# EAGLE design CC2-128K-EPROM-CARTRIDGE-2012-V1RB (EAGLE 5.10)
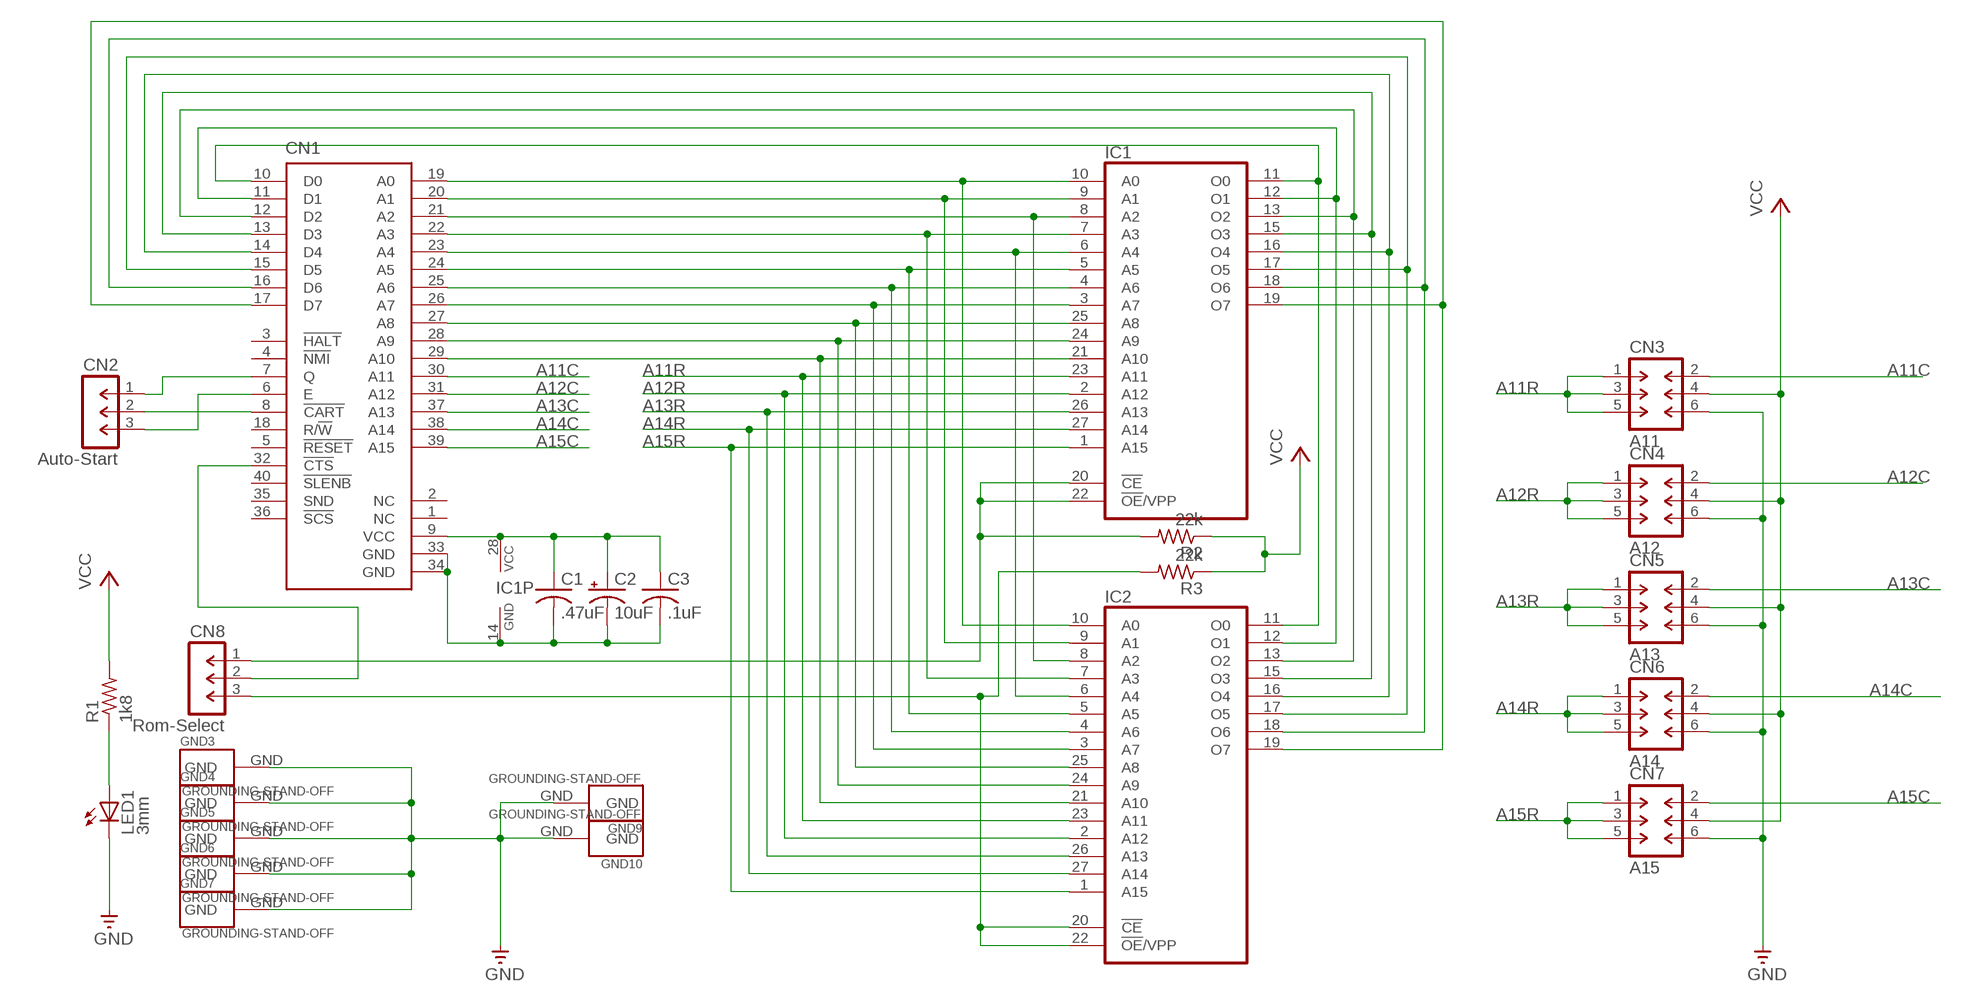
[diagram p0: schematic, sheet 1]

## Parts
C1  .47uF  NP-CAPACITOR-C050-025X075  [C050-025X075]
C2  10uF  P-CAPACITOR-CPOL-RADIAL-1  [CPOL-RADIAL-1]
C3  .1uF  NP-CAPACITOR-C050-025X075  [C050-025X075]
CN1  COCO3-CARTRIDGE-PLUG-MEDIUM  [EDGE-CARD-PLUG-40-MEDIUM]
CN2  Auto-Start  1X03-SIP-100-32  [SIL1X03-100]
CN3  A11  2X03-DIL-100-32  [DIL2X03-100]
CN4  A12  2X03-DIL-100-32  [DIL2X03-100]
CN5  A13  2X03-DIL-100-32  [DIL2X03-100]
CN6  A14  2X03-DIL-100-32  [DIL2X03-100]
CN7  A15  2X03-DIL-100-32  [DIL2X03-100]
CN8  Rom-Select  1X03-SIP-100-32  [SIL1X03-100]
GND3  GROUNDING-STAND-OFF  [STAND-OFF]
GND4  GROUNDING-STAND-OFF  [STAND-OFF]
GND5  GROUNDING-STAND-OFF  [STAND-OFF]
GND6  GROUNDING-STAND-OFF  [STAND-OFF]
GND7  GROUNDING-STAND-OFF  [STAND-OFF]
GND9  GROUNDING-STAND-OFF  [STAND-OFF]
GND10  GROUNDING-STAND-OFF  [STAND-OFF]
IC1  27C512D  [DIL28-6]
IC2  27C512D  [DIL28-6]
LED1  3mm  LED3MM  [LED3MM]
R1  1k8  RESISTOR  [0207/10]
R2  22k  RESISTOR  [0207/10]
R3  22k  RESISTOR  [0207/10]

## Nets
!CART: CN1.8(!CART) CN2.2
A11C: CN1.30(A11) CN3.2
A11R: CN3.1 CN3.3 CN3.5 IC1.23(A11) IC2.23(A11)
A12C: CN1.31(A12) CN4.2
A12R: CN4.1 CN4.3 CN4.5 IC1.2(A12) IC2.2(A12)
A13C: CN1.37(A13) CN5.2
A13R: CN5.1 CN5.3 CN5.5 IC1.26(A13) IC2.26(A13)
A14C: CN1.38(A14) CN6.2
A14R: CN6.1 CN6.3 CN6.5 IC1.27(A14) IC2.27(A14)
A15C: CN1.39(A15) CN7.2
A15R: CN7.1 CN7.3 CN7.5 IC1.1(A15) IC2.1(A15)
E: CN1.6(E) CN2.3
GND [power]: C1.2(-) C2.2(-) C3.2(-) CN1.33(GND) CN1.34(GND) CN3.6 CN4.6 CN5.6 CN6.6 CN7.6 GND3.GND GND4.GND GND5.GND GND6.GND GND7.GND GND9.GND GND10.GND IC1.14(GND) LED1.K(C)
N$1: CN1.19(A0) IC1.10(A0) IC2.10(A0)
N$2: CN1.20(A1) IC1.9(A1) IC2.9(A1)
N$3: CN1.21(A2) IC1.8(A2) IC2.8(A2)
N$4: CN1.22(A3) IC1.7(A3) IC2.7(A3)
N$5: CN1.23(A4) IC1.6(A4) IC2.6(A4)
N$6: CN1.24(A5) IC1.5(A5) IC2.5(A5)
N$7: CN1.25(A6) IC1.4(A6) IC2.4(A6)
N$8: CN1.26(A7) IC1.3(A7) IC2.3(A7)
N$9: CN1.27(A8) IC1.25(A8) IC2.25(A8)
N$10: CN1.28(A9) IC1.24(A9) IC2.24(A9)
N$11: CN1.29(A10) IC1.21(A10) IC2.21(A10)
N$12: CN1.10(D0) IC1.11(O0) IC2.11(O0)
N$13: CN1.11(D1) IC1.12(O1) IC2.12(O1)
N$14: CN1.12(D2) IC1.13(O2) IC2.13(O2)
N$15: CN1.13(D3) IC1.15(O3) IC2.15(O3)
N$16: CN1.14(D4) IC1.16(O4) IC2.16(O4)
N$17: CN1.15(D5) IC1.17(O5) IC2.17(O5)
N$18: CN1.16(D6) IC1.18(O6) IC2.18(O6)
N$19: CN1.17(D7) IC1.19(O7) IC2.19(O7)
N$24: LED1.A R1.1
N$25: CN1.32(!CTS) CN8.2
Q: CN1.7(Q) CN2.1
ROM1: CN8.1 IC1.20(!CE) IC1.22(!OE!/VPP) R2.2
ROM2: CN8.3 IC2.20(!CE) IC2.22(!OE!/VPP) R3.2
VCC [power]: C1.1(+) C2.1(+) C3.1(+) CN1.9(VCC) CN3.4 CN4.4 CN5.4 CN6.4 CN7.4 IC1.28(VCC) R1.2 R2.1 R3.1
Unconnected: CN1.1(NC) CN1.2(NC) CN1.3(!HALT) CN1.4(!NMI) CN1.5(!RESET) CN1.18(R/!W) CN1.35(SND) CN1.36(!SCS) CN1.40(!SLENB)

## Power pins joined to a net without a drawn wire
GND: IC2.14(GND)
VCC: IC2.28(VCC)

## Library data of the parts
C1 C3 = GIMEchip-Capacitor:NP-CAPACITOR: NON-POLARIZED CAPACITOR
C2 = GIMEchip-Capacitor:P-CAPACITOR: POLARIZED CAPACITOR
CN1 = GIMEchip-TRS-80-CoCo-3-Program-Pak-Cartridge:COCO3-CARTRIDGE-PLUG: CoCo 3 Program Pak Cartridge Plug - http://www.GIMEchip.com/ Tandy Radio Shack TRS-80 Color Computer 3 Program Pak Cartridge Plug (Edge-Card) E.A.G.L.E. Library Part created by John Eric Turner & His Father - sales@gimechip.com 40-Pin Edge-Card sharing the same pinout as the Program Pak Cartridge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
CN2 CN8 = GIMEchip-Header-Generic:1X03: MALE HEADER
CN3-CN7 = GIMEchip-Header-Generic:2X03: MALE HEADER
GND3-GND7 GND9 GND10 = GIMEchip-Grounding:GROUNDING
IC1 IC2 = GIMEchip-EPROM:27C512D: MEMORY
LED1 = Copy of GCC-CC3-512KCBR-0001:LED3MM: LED
R1-R3 = GIMEchip-Resistor:RESISTOR

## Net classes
0 default: width 0.254 mm, clearance 0.203 mm
1 power: width 0.762 mm, clearance 0.203 mm

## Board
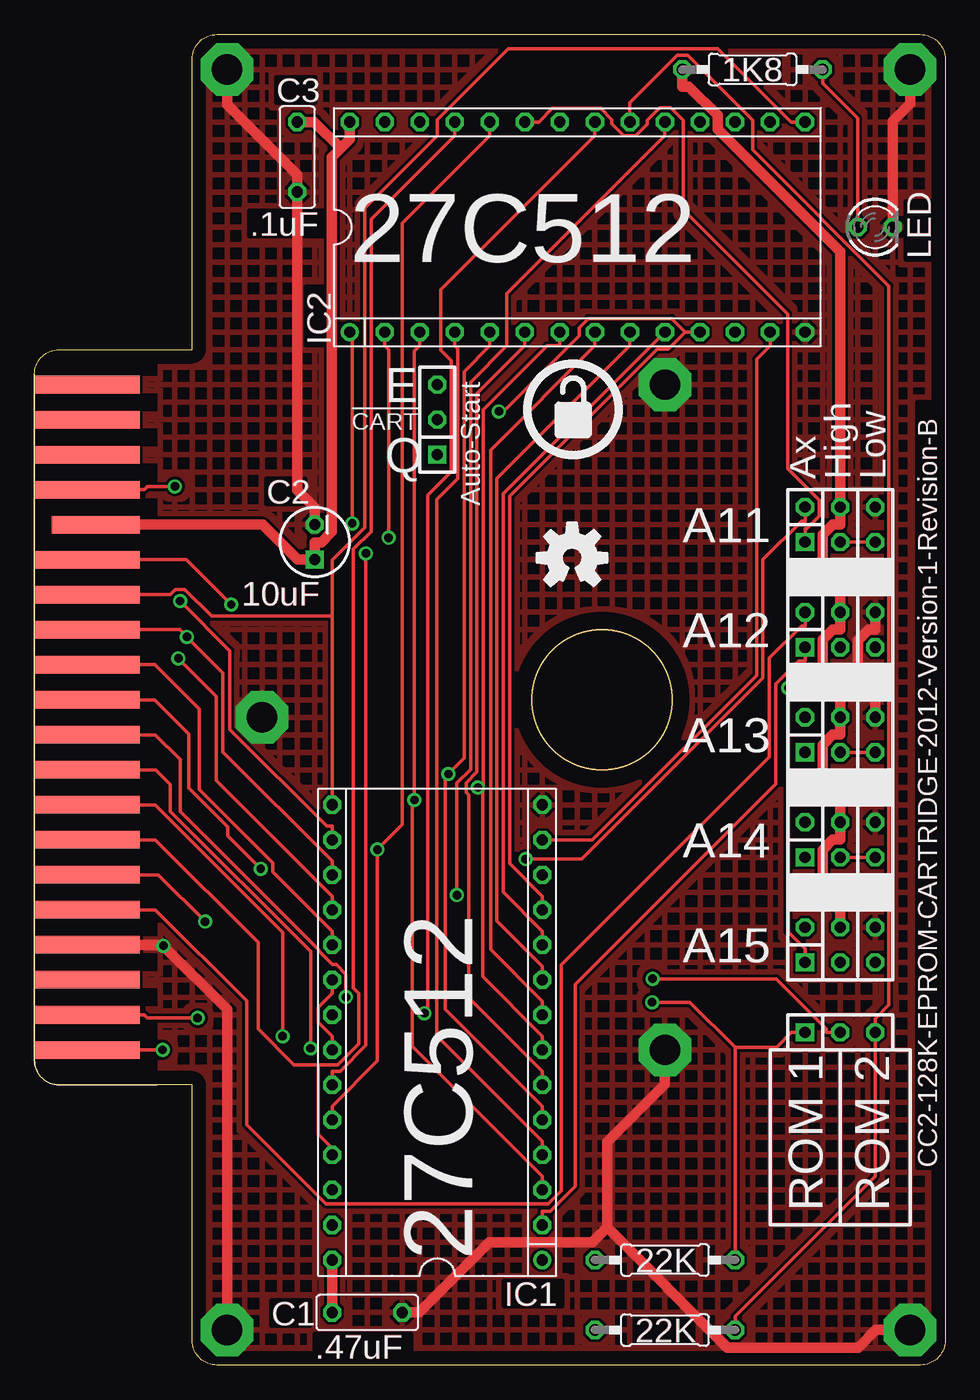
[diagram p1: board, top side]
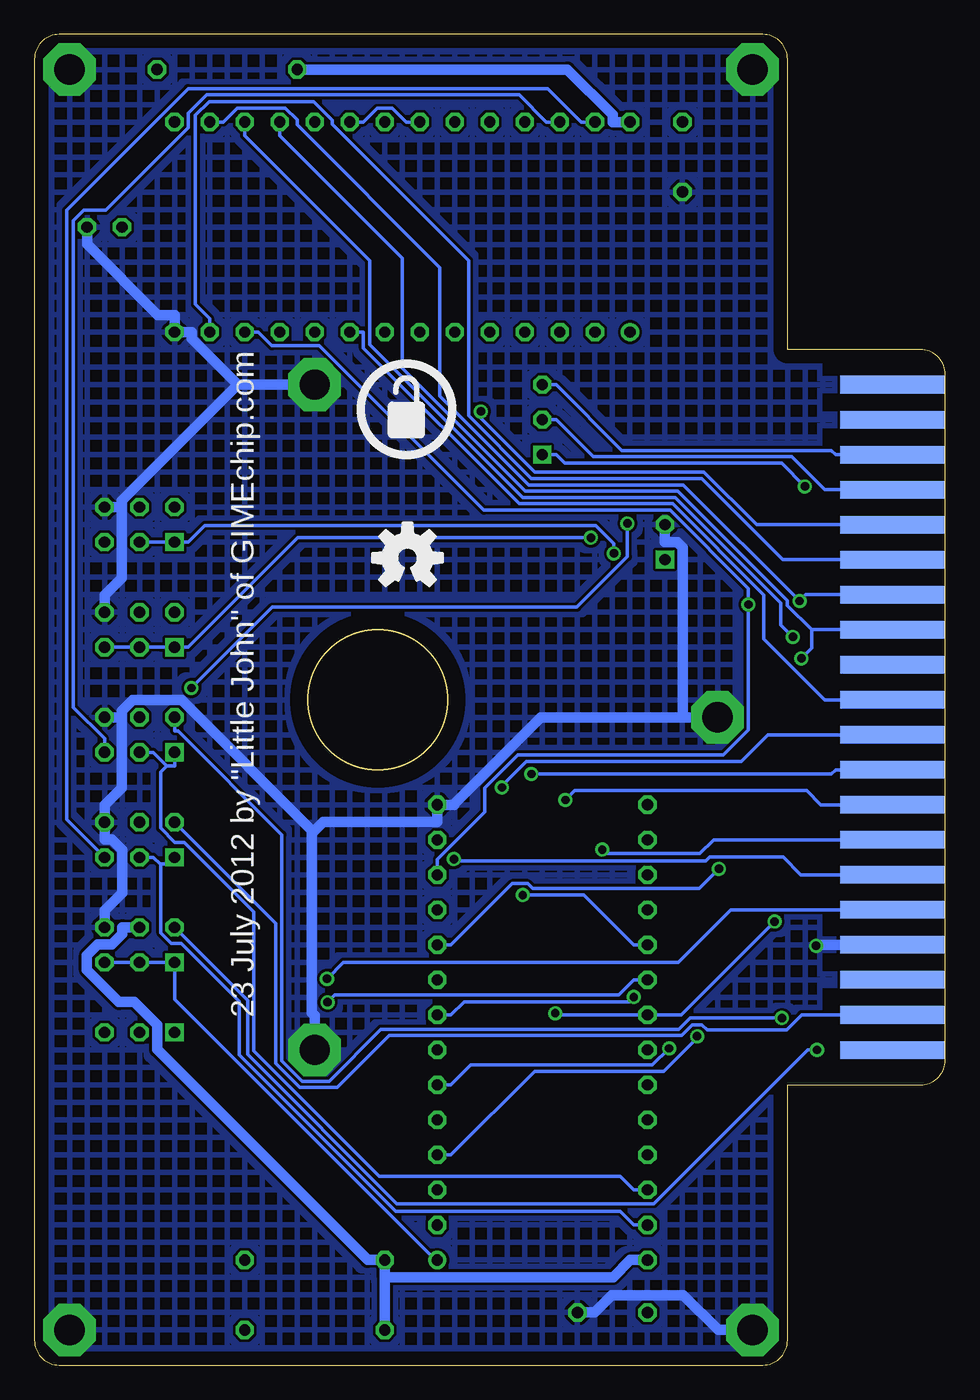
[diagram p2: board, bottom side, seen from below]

Size 66.04 x 96.52 mm. Coordinates in mm from the lower left corner, seen from the top.
Outline: 11.43,20.32 1.8,20.32 arc-90 0,22.12 0,71.86 arc-90 1.8,73.66 11.43,73.66 11.43,94.72 arc-90 13.23,96.52 64.24,96.52 arc-90 66.04,94.72 66.04,1.8 arc-90 64.24,0 13.23,0 arc-90 11.43,1.8 11.43,20.32
Outline: circle at 41.15,48.26 radius 5.08
Copper layers (1*16): Top 0.035mm / dielectric 1.5mm / Bottom 0.035mm
Design rules "default": minimum track width 10mil, minimum drill 24mil, track to track 8mil, track to pad 8mil, pad to pad 8mil, via to via 8mil, smd to smd 8mil, copper to edge 40mil, drill to drill 8mil, minimum pad ring 10mil, minimum via ring 8mil, stop-mask expansion 4mil, vias tented up to drill 0mil, thermal gap 10mil
tRestrict: area 34.8,41.9 to 47.5,54.6
bRestrict: area 34.8,41.9 to 47.5,54.6

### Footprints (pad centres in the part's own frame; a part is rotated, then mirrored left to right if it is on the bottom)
C050-025X075 = drill 0.813 octagon: 1 -2.54,0; 2 2.54,0
CPOL-RADIAL-1 = drill 0.813 square: 1 1.27,0 | drill 0.813 octagon: 2 -1.27,0
EDGE-CARD-PLUG-40-MEDIUM = smd 7.62 x 1.27: 1 3.81,24.13; 3 3.81,21.59; 5 3.81,19.05; 7 3.81,16.51; 11 3.81,11.43; 13 3.81,8.89; 15 3.81,6.35; 17 3.81,3.81; 19 3.81,1.27; 21 3.81,-1.27; 23 3.81,-3.81; 25 3.81,-6.35; 27 3.81,-8.89; 29 3.81,-11.43; 31 3.81,-13.97; 33 3.81,-16.51; 35 3.81,-19.05; 37 3.81,-21.59; 39 3.81,-24.13 | smd 7.62 x 1.27 bottom: 2 3.81,24.13; 4 3.81,21.59; 6 3.81,19.05; 8 3.81,16.51; 10 3.81,13.97; 12 3.81,11.43; 14 3.81,8.89; 16 3.81,6.35; 18 3.81,3.81; 20 3.81,1.27; 22 3.81,-1.27; 24 3.81,-3.81; 26 3.81,-6.35; 28 3.81,-8.89; 30 3.81,-11.43; 32 3.81,-13.97; 34 3.81,-16.51; 36 3.81,-19.05; 38 3.81,-21.59; 40 3.81,-24.13 | smd 6.35 x 1.27: 9 4.445,13.97
SIL1X03-100 = drill 0.813 square: 1 -2.54,0 | drill 0.813 octagon: 2 0,0; 3 2.54,0
DIL2X03-100 = drill 0.813 square: 1 -2.54,-1.27 | drill 0.813 octagon: 2 -2.54,1.27; 3 0,-1.27; 4 0,1.27; 5 2.54,-1.27; 6 2.54,1.27
STAND-OFF = drill 2.2 pad 3.81 octagon: GND 0,0
DIL28-6 = drill 0.813 round: 1 -16.51,-7.62 | drill 0.813 octagon: 2 -13.97,-7.62; 3 -11.43,-7.62; 4 -8.89,-7.62; 5 -6.35,-7.62; 6 -3.81,-7.62; 7 -1.27,-7.62; 8 1.27,-7.62; 9 3.81,-7.62; 10 6.35,-7.62; 11 8.89,-7.62; 12 11.43,-7.62; 13 13.97,-7.62; 14 16.51,-7.62; 15 16.51,7.62; 16 13.97,7.62; 17 11.43,7.62; 18 8.89,7.62; 19 6.35,7.62; 20 3.81,7.62; 21 1.27,7.62; 22 -1.27,7.62; 23 -3.81,7.62; 24 -6.35,7.62; 25 -8.89,7.62; 26 -11.43,7.62; 27 -13.97,7.62; 28 -16.51,7.62
LED3MM = drill 0.813 octagon: A -1.27,0; K 1.27,0
0207/10 = drill 0.813 octagon: 1 -5.08,0; 2 5.08,0

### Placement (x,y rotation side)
C1  24.13,3.81 0 top
C2  20.32,59.69 270 top
C3  19.05,87.63 270 top
CN1  0,46.99 0 top
CN2  29.21,68.58 90 top
CN3  58.42,60.96 0 top
CN4  58.42,53.34 0 top
CN5  58.42,45.72 0 top
CN6  58.42,38.1 0 top
CN7  58.42,30.48 0 top
CN8  58.42,24.13 0 top
GND3  13.97,93.98 0 top
GND4  13.97,2.54 0 top
GND5  45.72,71.12 0 top
GND6  45.72,22.86 0 top
GND7  16.51,46.99 0 top
GND9  63.5,93.98 0 top
GND10  63.5,2.54 0 top
IC1  29.21,24.13 90 top
IC2  39.37,82.55 0 top
LED1  60.96,82.55 0 top
R1  52.07,93.98 180 top
R2  45.72,7.62 0 top
R3  45.72,2.54 0 top
U$1  [OSHWLOGO_0.3]  39.07,69.32 0 top
U$2  [OSHWLOGO_0.3]  39.07,69.32 0 bottom
U$3  [OSHWLOGO_TOL_0.2]  38.99,58.55 0 top
U$4  [OSHWLOGO_TOL_0.2]  38.99,58.55 0 bottom

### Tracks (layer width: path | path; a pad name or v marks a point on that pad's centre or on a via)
!CART
  Bottom 0.254: CN2.2 28.22,68.58 25.53,65.89 11.13,65.89 8.74,63.5 CN1.8
A11C  (via drill 0.61 pad 1.02)
  Top 0.254: v35.62,36.7 39.69,36.7 52.83,49.84 52.83,58.43 55.63,61.24 55.88,61.24 CN3.2
  Bottom 0.254: CN1.30 10.47,35.56 11.76,36.85 17.06,36.85 17.36,36.55 35.47,36.55 v35.62,36.7
A11R  (via drill 0.61 pad 1.02)
  Top 0.254: v24.03,58.88 24.03,23.18 22.16,21.31 21.59,21.31 IC1.23 | CN3.1 55.88,60.68 55.98,60.68 56.9,61.6 56.9,62.74 54.61,65.03 54.61,76.24 47.05,83.8 47.05,90.29 46.12,91.21 45.35,91.21 44.45,90.31 44.45,90.03 43.6,89.18 42.74,89.18 41.87,90.06 41.87,90.35 41.05,91.16 37.54,91.16 36.55,90.17 IC2.23 | CN3.3 CN3.5
  Bottom 0.254: v24.03,58.88 24.03,59.59 25.34,60.9 53.68,60.9 54.89,59.69 CN3.1 CN3.3
A12C
  Top 0.254: CN1.31 8.76,33.02 15.39,26.4 15.39,17.44 21.11,11.71 37.26,11.71 38.2,12.65 38.2,29.04 53.28,44.12 53.28,51.27 55.63,53.62 55.88,53.62 CN4.2
A12R  (via drill 0.61 pad 1.02)
  Top 0.254: IC1.2 36.83,11.15 37.39,11.15 39.2,12.96 39.2,27.6 53.74,42.14 53.74,49.39 55.43,51.08 55.88,51.08 CN4.1 | v25.68,60.02 25.68,73.65 25.4,73.94 IC2.2
  Bottom 0.254: v25.68,60.02 46.94,60.02 54.89,52.07 CN4.1 56.87,52.07 CN4.3 CN4.5
A13C  (via drill 0.61 pad 1.02)
  Top 0.254: v11.84,25.18 8.17,25.18 7.95,25.4 CN1.37
  Bottom 0.254: v11.84,25.18 18.49,25.18 19.31,24.36 40.91,24.36 44.68,20.59 46.63,20.59 48.1,22.06 48.1,38.46 55.63,46 55.88,46 CN5.2
A13R
  Top 0.254: CN5.3 CN5.5
  Bottom 0.254: 56.44,43.46 56.88,43.01 56.88,38.94 55.86,37.92 55.17,37.92 50.13,32.88 50.13,22.79 41.03,13.69 23.57,13.69 22.58,12.7 IC1.26 | 56.44,43.46 55.88,43.46 CN5.1 | 56.44,43.46 57.43,44.45 CN5.3 | CN5.5 60.96,45.44 63.23,47.71 63.23,83 62.46,83.77 60.88,83.77 54.89,89.76 54.89,90.8 53.55,92.13 30.89,92.13 28.93,90.17 IC2.26
A14C
  Bottom 0.254: CN6.2 48.55,32.04 48.55,21.87 46.82,20.14 44.07,20.14 40.31,23.9 19.12,23.9 18.33,24.69 17.64,24.69 17.27,24.32 11.5,24.32 10.42,25.4 CN1.38
A14R
  Top 0.254: CN6.3 CN6.5
  Bottom 0.254: 56.88,36.34 56.88,31.33 56.12,30.57 55.39,30.57 51.2,26.38 51.2,22.5 39.86,11.15 23.57,11.15 22.58,10.16 IC1.27 | IC2.27 26.39,90.17 28.81,92.59 54.89,92.59 63.72,83.76 63.72,39.59 CN6.5 | 56.88,36.34 56.93,36.34 57.43,36.83 CN6.3 | 56.88,36.34 55.88,36.34 CN6.1
A15C  (via drill 0.61 pad 1.02)
  Top 0.254: CN1.39 v9.3,22.86
  Bottom 0.254: CN7.2 50.59,26.46 50.59,22.53 39.76,11.7 21.12,11.7 9.96,22.86 v9.3,22.86
A15R  (via drill 0.61 pad 1.02)
  Top 0.254: IC2.1 23.04,74.75 v23.04,61.05 | v54.66,49.11 54.66,31.42 55.88,30.2 CN7.1
  Bottom 0.254: v23.04,61.05 23.04,58.64 26.7,54.98 48.79,54.98 v54.66,49.11 | IC1.1 36.97,7.62 55.88,26.53 CN7.1 57.43,29.21 CN7.3 CN7.5
E
  Bottom 0.254: CN1.6 7.95,66.04 8.26,66.34 23.44,66.34 28.22,71.12 CN2.3
GND  (via drill 0.61 pad 1.02)
  Top 0.762: GND3.GND 13.97,91.42 19.05,86.33 C3.2 19.05,63.48 20.32,62.2 C2.2 | GND6.GND 45.72,20.37 41.53,16.18 41.53,9.99 | GND10.GND 61.01,2.54 59.74,1.27 50.24,1.27 41.53,9.99 | 41.53,9.99 40.43,8.89 32.99,8.89 27.91,3.81 C1.2 | GND9.GND 63.5,91.49 62.23,90.22 LED1.K | CN5.6 60.96,48.23 59.69,49.51 59.69,52.56 60.49,53.37 60.96,53.37 CN4.6 | CN1.34 9.28,30.48 v9.36,30.41 13.97,25.79 13.97,5.03 GND4.GND
  Bottom 0.762: 19.03,46.99 29.31,46.99 35.58,40.72 35.58,40.64 IC1.14 36.83,39.4 45.1,39.4 45.81,38.69 | 19.03,46.99 GND7.GND | 19.03,46.99 19.03,59.31 19.44,59.72 20.32,59.72 C2.2 | LED1.K 62.23,81.31 57.1,76.17 55.88,76.17 IC2.14 54.63,74.93 54.63,74.46 51.29,71.12 | GND4.GND 16.46,2.54 18.98,5.06 24.18,5.06 25.43,3.81 C1.2 | CN4.6 60.96,55.85 59.71,57.1 59.71,62.23 | 51.29,71.12 59.71,62.7 59.71,62.23 | 51.29,71.12 GND5.GND | 59.71,62.23 CN3.6 | 59.71,46.99 59.71,41.86 60.96,40.62 CN6.6 60.96,38.75 60.96,38.12 60.44,38.12 59.69,37.37 59.69,34.27 60.96,32.99 CN7.6 | 45.81,38.69 55.37,48.24 58.93,48.24 59.71,47.46 59.71,46.99 | GND6.GND 45.72,25.35 45.93,25.56 45.93,38.57 45.81,38.69 | CN1.34 9.28,30.48 v9.36,30.41 | 59.71,46.99 CN5.6
  pour Top (hatched): -1.27,0 66.04,0 66.04,96.52 -1.27,96.52
  pour Bottom (hatched): -1.27,0 67.31,0 67.31,96.52 -1.27,96.52
N$1  (via drill 0.61 pad 1.02)
  Top 0.254: IC2.10 34,63.21 34,34.3 36.83,31.47 IC1.10 | v16.41,35.99 14.03,38.37 14.03,39.02 11.2,41.85 11.2,45.79 8.73,48.26 CN1.19
  Bottom 0.254: v16.41,35.99 17.84,34.57 29.92,34.57 30.29,34.93 31.39,34.93 35.84,30.48 IC1.10
N$2
  Top 0.254: IC1.9 36.83,28.93 33.53,32.23 33.53,64.29 43.18,73.94 IC2.9
  Bottom 0.254: CN1.20 7.95,48.26 8.74,48.26 13.15,52.67 13.15,55.86 19.77,62.48 30.9,62.48 42.19,73.77 42.19,74.93 IC2.9
N$3  (via drill 0.61 pad 1.02)
  Top 0.254: IC1.8 36.83,26.39 33.07,30.15 33.07,66.37 40.64,73.94 IC2.8 | v22.58,26.7 22.58,28.35 21.88,29.05 21.59,29.05 20.6,30.04 20.6,30.12 10.56,40.16 10.56,43.94 8.78,45.72 CN1.21
  Bottom 0.254: IC1.8 35.84,25.4 34.88,26.36 22.92,26.36 v22.58,26.7
N$4  (via drill 0.61 pad 1.02)
  Top 0.254: 32.5,41.89 32.53,41.92 32.53,69.29 37.18,73.94 38.1,73.94 IC2.7 | v32.15,41.89 32.5,41.89 | 32.5,41.89 32.5,28.18 36.83,23.85 IC1.7
  Bottom 0.254: CN1.22 12.86,45.72 14.8,43.79 30.37,43.79 32.15,42.01 v32.15,41.89
N$5  (via drill 0.61 pad 1.02)
  Top 0.254: IC1.6 36.83,21.31 31.5,26.64 31.5,41.36 31.31,41.55 31.31,42.24 32.08,43 32.08,70.45 35.56,73.94 IC2.6 | v20.02,22.97 20.02,30 9.86,40.17 9.86,42.11 8.79,43.18 CN1.23
  Bottom 0.254: IC1.6 35.84,20.32 34.39,21.77 21.23,21.77 v20.02,22.97
N$6  (via drill 0.61 pad 1.02)
  Top 0.254: IC2.5 33.02,73.94 31.16,72.08 31.16,44.03 v30.01,42.88 29.79,42.66 29.79,25.81 36.83,18.77 IC1.5
  Bottom 0.254: CN1.24 7.95,43.18 8.26,42.88 v30.01,42.88
N$7  (via drill 0.61 pad 1.02)
  Top 0.254: CN1.25 8.74,40.64 17.99,31.39 v17.99,23.85 | IC1.4 36.83,16.23 29.17,23.89 29.17,62.77 30.7,64.3 30.7,73.72 30.48,73.94 IC2.4
  Bottom 0.254: v17.99,23.85 17.99,23.73 20.41,21.31 29.77,21.31 35.84,15.24 IC1.4
N$8  (via drill 0.61 pad 1.02)
  Top 0.254: v27.55,40.99 27.39,40.83 27.39,23.13 36.83,13.69 IC1.3 | v27.55,40.99 27.55,73.55 27.94,73.94 IC2.3 | v27.55,40.99
  Bottom 0.254: v27.55,40.99 26.87,41.66 10.04,41.66 9.02,40.64 7.95,40.64 CN1.26
N$9
  Top 0.254: 20.58,21.79 21.99,21.79 23.5,23.3 23.5,26.96 23.12,27.35 23.12,59.18 24.41,60.48 24.41,83.11 30.48,89.18 IC2.25 | 20.58,21.79 18.81,21.79 16.22,24.38 16.22,30.64 8.76,38.1 CN1.27 | 20.58,21.79 20.58,16.74 21.59,15.73 IC1.25
N$10  (via drill 0.61 pad 1.02)
  Top 0.254: IC2.24 33.02,89.18 26.68,82.84 26.68,39.2 v24.87,37.39 24.87,22.05 21.59,18.77 IC1.24
  Bottom 0.254: CN1.28 16.78,38.1 17.78,37.1 24.57,37.1 v24.87,37.39
N$11  (via drill 0.61 pad 1.02)
  Top 0.254: v28.28,25.52 28.52,25.77 28.52,63.09 30.23,64.79 30.23,72.85 29.46,73.62 29.46,78 40.64,89.18 IC2.21 | v12.37,32.17 8.98,35.56 CN1.29
  Bottom 0.254: v28.28,25.52 28.16,25.4 22.58,25.4 IC1.21 19.14,25.4 v12.37,32.17
N$12  (via drill 0.61 pad 1.02)
  Top 0.254: 47.18,74.94 45.95,73.71 45.15,73.71 34.46,63.02 34.46,36.38 36.83,34.01 IC1.11 | 47.18,74.94 46.2,75.92 40.17,75.92 39.49,75.24 39.49,74.68 33.99,69.18 v33.67,69.18 | 47.18,74.94 47.75,74.94 47.76,74.93 IC2.11
  Bottom 0.254: v33.67,69.18 33.67,68.7 29.77,64.79 17.5,64.79 13.67,60.96 CN1.10
N$13  (via drill 0.61 pad 1.02)
  Top 0.254: v14.27,55.17 11.01,58.42 7.95,58.42 CN1.11
  Bottom 0.254: IC2.12 49.81,74.93 48.82,73.94 45.38,73.94 33.45,62.02 19.96,62.02 14.27,56.33 v14.27,55.17 14.27,46.06 16.08,44.25 31,44.25 33.39,41.86 33.39,40.12 36.83,36.68 36.83,36.55 IC1.12
N$14
  Top 0.254: IC2.13 53.34,73.94 52.37,72.97 52.37,50.03 40.44,38.1 37.82,38.1 IC1.13
  Bottom 0.254: CN1.12 11.78,58.42 17.66,64.31 30,64.31 34.56,68.86 34.56,80.12 44.45,90.02 44.45,90.3 45.79,91.64 53.38,91.64 54.37,90.65 54.37,76.95 53.34,75.92 IC2.13
N$15
  Top 0.254: 21.59,54.32 12.85,54.32 10.91,56.26 10.21,56.26 9.84,55.88 7.95,55.88 CN1.13 | IC2.15 54.89,90.17 49.56,95.5 34.37,95.5 29.21,90.34 29.21,89.18 23.95,83.92 23.95,60.74 21.59,58.38 21.59,54.32 | 21.59,54.32 21.59,41.63 IC1.15
N$16  (via drill 0.61 pad 1.02)
  Top 0.254: v10.56,55.42 14.17,51.81 14.17,46.1 21.18,39.09 21.59,39.09 IC1.16
  Bottom 0.254: CN1.14 10.1,55.88 v10.56,55.42 18.99,63.85 30.19,63.85 36.64,70.3 36.64,79.62 46.99,89.97 46.99,90.33 47.85,91.18 51.34,91.18 52.35,90.17 IC2.16
N$17  (via drill 0.61 pad 1.02)
  Top 0.254: IC1.17 21.59,36.55 13.66,44.48 13.66,50.21 v11.05,52.82 10.53,53.34 CN1.15
  Bottom 0.254: v11.05,52.82 11.93,53.7 11.93,55.28 19.58,62.93 30.64,62.93 41.72,74.01 41.72,80.1 50.8,89.18 IC2.17
N$18  (via drill 0.61 pad 1.02)
  Top 0.254: IC1.18 21.59,34.01 13.2,42.4 13.2,48.49 v10.43,51.26
  Bottom 0.254: 9.69,53.34 CN1.16 | 9.69,53.34 11.46,55.11 11.46,55.46 19.39,63.39 30.46,63.39 39.37,72.31 39.37,80.29 48.26,89.18 IC2.18 | v10.43,51.26 9.69,52 9.69,53.34
N$19  (via drill 0.61 pad 1.02)
  Top 0.254: CN1.17 8.72,50.8 11.95,47.58 11.95,41.75 | 11.95,41.75 | 11.95,41.75 17.28,36.41 17.28,35.78 21.59,31.47 IC1.19 | v30.63,34.1 30.63,42.21 31.62,43.19 31.62,71.31 34.25,73.94 34.25,77.71 45.72,89.18 IC2.19
  Bottom 0.254: IC1.19 22.58,30.48 26.2,34.1 v30.63,34.1
N$24
  Top 0.254: R1.1 57.15,92.99 59.69,90.45 LED1.A
N$25  (via drill 0.61 pad 1.02)
  Top 0.254: v44.83,28.02 53.79,28.02 57.43,24.38 57.43,24.13 CN8.2
  Bottom 0.254: CN1.32 15.56,33.02 19.37,29.21 43.64,29.21 v44.83,28.02
Q  (via drill 0.61 pad 1.02)
  Top 0.254: CN1.7 7.95,63.5 8.19,63.74 v10.18,63.74
  Bottom 0.254: v10.18,63.74 11.86,65.42 27.59,65.42 28.22,66.04 CN2.1
ROM1  (via drill 0.61 pad 1.02)
  Top 0.254: 50.8,23.05 47.53,26.32 v44.79,26.32 | 50.8,23.05 50.8,8.61 R2.2 | 50.8,23.05 53.81,23.05 54.89,24.13 CN8.1 | IC1.22 21.59,23.85 20.59,24.85 20.59,25.95 21.59,26.95 IC1.20
  Bottom 0.254: v44.79,26.32 44.26,26.85 23.67,26.85 22.58,27.94 IC1.20
ROM2
  Top 0.254: R3.2 50.8,3.53 60.96,13.69 CN8.3 60.96,25.12 61.95,26.11 61.95,78.26 52.07,88.15 52.07,90.31 47.38,95.01 46.61,95.01 43.18,91.58 IC2.20
  Bottom 0.254: IC2.22 39.09,90.17 40.08,91.16 41.2,91.16 42.19,90.17 IC2.20
VCC
  Top 0.762: 22.2,88.27 21.57,87.63 21.57,60.44 20.79,59.66 20.32,59.66 C2.1 19.07,58.42 16.54,60.96 CN1.9 | 22.2,88.27 22.86,88.92 IC2.28 | 22.2,88.27 20.3,90.17 C3.1 | CN7.4 58.42,32.99 57.15,34.27 57.15,37.37 57.9,38.12 58.42,38.12 CN6.4 58.42,40.62 57.15,41.88 57.15,44.99 57.9,45.74 58.42,45.74 58.42,46.37 CN5.4 58.42,48.23 57.15,49.51 57.15,52.61 57.9,53.37 58.42,53.37 CN4.4 58.42,55.85 57.15,57.12 57.15,60.23 57.9,60.98 58.42,60.98 CN3.4 58.42,80.77 49.53,89.66 49.53,90.66 47.46,92.73 46.99,92.73 R1.2 | C1.1 IC1.28
  Bottom 0.762: 40.64,6.38 24.08,6.38 22.84,7.62 IC1.28 | 40.64,6.38 R3.1 | 40.64,6.38 R2.1 41.88,7.62 57.15,22.89 57.15,24.68 58.8,26.33 59.92,26.33 62.24,28.65 62.24,29.73 61.47,30.5 60.44,30.5 59.66,31.28 59.66,31.75 CN7.4 | IC2.28 24.11,90.17 24.11,90.69 27.4,93.98 R1.2

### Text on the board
Top: 1K8 | C3 | .1uF | LED | IC2 | C2 | 10uF | CC2-128K-EPROM-CARTRIDGE-2012-Version-1-Revision-B | 22K | IC1 | C1 | 22K | .47uF
tPlace: 1K8 | C3 | .1uF | 27C512 | LED | IC2 | E | !CART | Q | Ax | High | Low | C2 | Auto-Start | A11 | 10uF | A12 | A13 | A14 | A15 | CC2-128K-EPROM-CARTRIDGE-2012-Version-1-Revision-B | ROM 1 | ROM 2 | 27C512 | 22K | IC1 | C1 | 22K | .47uF
bPlace: 23 July 2012 by "Little John" of GIMEchip.com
